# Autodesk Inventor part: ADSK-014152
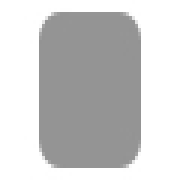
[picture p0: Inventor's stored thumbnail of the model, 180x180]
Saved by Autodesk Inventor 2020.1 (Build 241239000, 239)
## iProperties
Created: 2019-01
Part Number: ADSK-014152
Material: Stahl, weich
Document SubType Name: Modeling
Designer: lutzd
Language: de-DE
Size Designation: 5 x 39,384472 x 39,384472
Categories: <MemberInstance><Categories><Category DisplayName="Sonstige Bauteile" InternalName="5aa15e00-363f-49f2-933f-16f664388e3f" Mnemonic="OTHER"><Category DisplayName
Mass: 60.0398 g
Surface Area: 38.0412 cm^2
Volume: 7.64838 cm^3
Density: 7.85 g/cm^3
Appearance: Halbpoliert
Dimensions: 39,4x39,4x5 mm
Mass: 0,06 kg
DocNumber: ADSK-014152
Folder: 01 - Themengebiete\Simplification\01 - Packaging machine\
VDS_Category: 3D Komponenten
VDS_NumSchm: Autodesk
IsCustomPart: 1
Title: end cap
Author: lutzd
Revision Number: -
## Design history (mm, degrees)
sketch "Sketch1"
  geometry: L1 (0, 20.175)-(0, -21.446); L2 (-20.203, 0)-(20.169, 0); L3 (-19.692, 19.692)-(19.692, 19.692); L4 (19.692, 19.692)-(19.692, -19.692); L5 (19.692, -19.692)-(-19.692, -19.692); L6 (-19.692, -19.692)-(-19.692, 19.692); 1 further point
  constraints: 12 end point, 2 horizontal, 2 parallel, 2 point on line, 1 perpendicular, 1 vertical
  dimensions: "d0" = 39.38447 distance between parallel lines of L5 L3 (= height); "d1" = 19.69224 distance between parallel lines of L2 L3 (= 0.5 x height); "d2" = 39.38447 distance between parallel lines of L6 L4 (= width); "d3" = 19.69224 distance between parallel lines of L6 L1 (= 0.5 x width)
extrude "Extrusion1" new body sketch "Sketch1" distance "d4" = 5 (= thickness); taper "d5" = 0 deg
fillet "Fillet1" dims "d6" = 5 (= fillet), "d7" = 0, "fillet" = 5 [user parameter; used in 1 equation term]
chamfer "Chamfer1" distance "d8" = 0 (computed from chamfer); stored, may be unused: second distance "d9" = 2, angle "d10" = 45 deg; dims "d11" = 0, "chamfer" = 0 [user parameter; used in 1 equation term]
body "Solid1"
other parameters: "thickness" = 5 [user parameter; used in 1 equation term], "width" = 39.38447 [user parameter; used in 2 equation terms], "height" = 39.38447 [user parameter; used in 2 equation terms]
